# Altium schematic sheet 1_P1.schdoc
size 307 x 218 mm; Symbol: Drawing-Symbol_A4; Device: Drawing-Symbol_A4; Company: wenfeng110402; Drawed: 叶文峰; Reviewed: 叶文峰; Version: V1.0; Page Size: A4; @Project Name: hackpod; @Page Count: 1; @Update Date: 2025-11-23; @Create Date: 2025-11-21; @Schematic Name: Schematic1; @Page No: 1; @Page Name: P1; @Board Name: Board1; @Create Time: 22:44:27; @Update Time: 14:09:08; Title Block Position: 3; Size: A4; Width: 1170; Height: 825; Region Start: 1; X Region Count: 6; Y Region Count: 4; Blade Width: 10
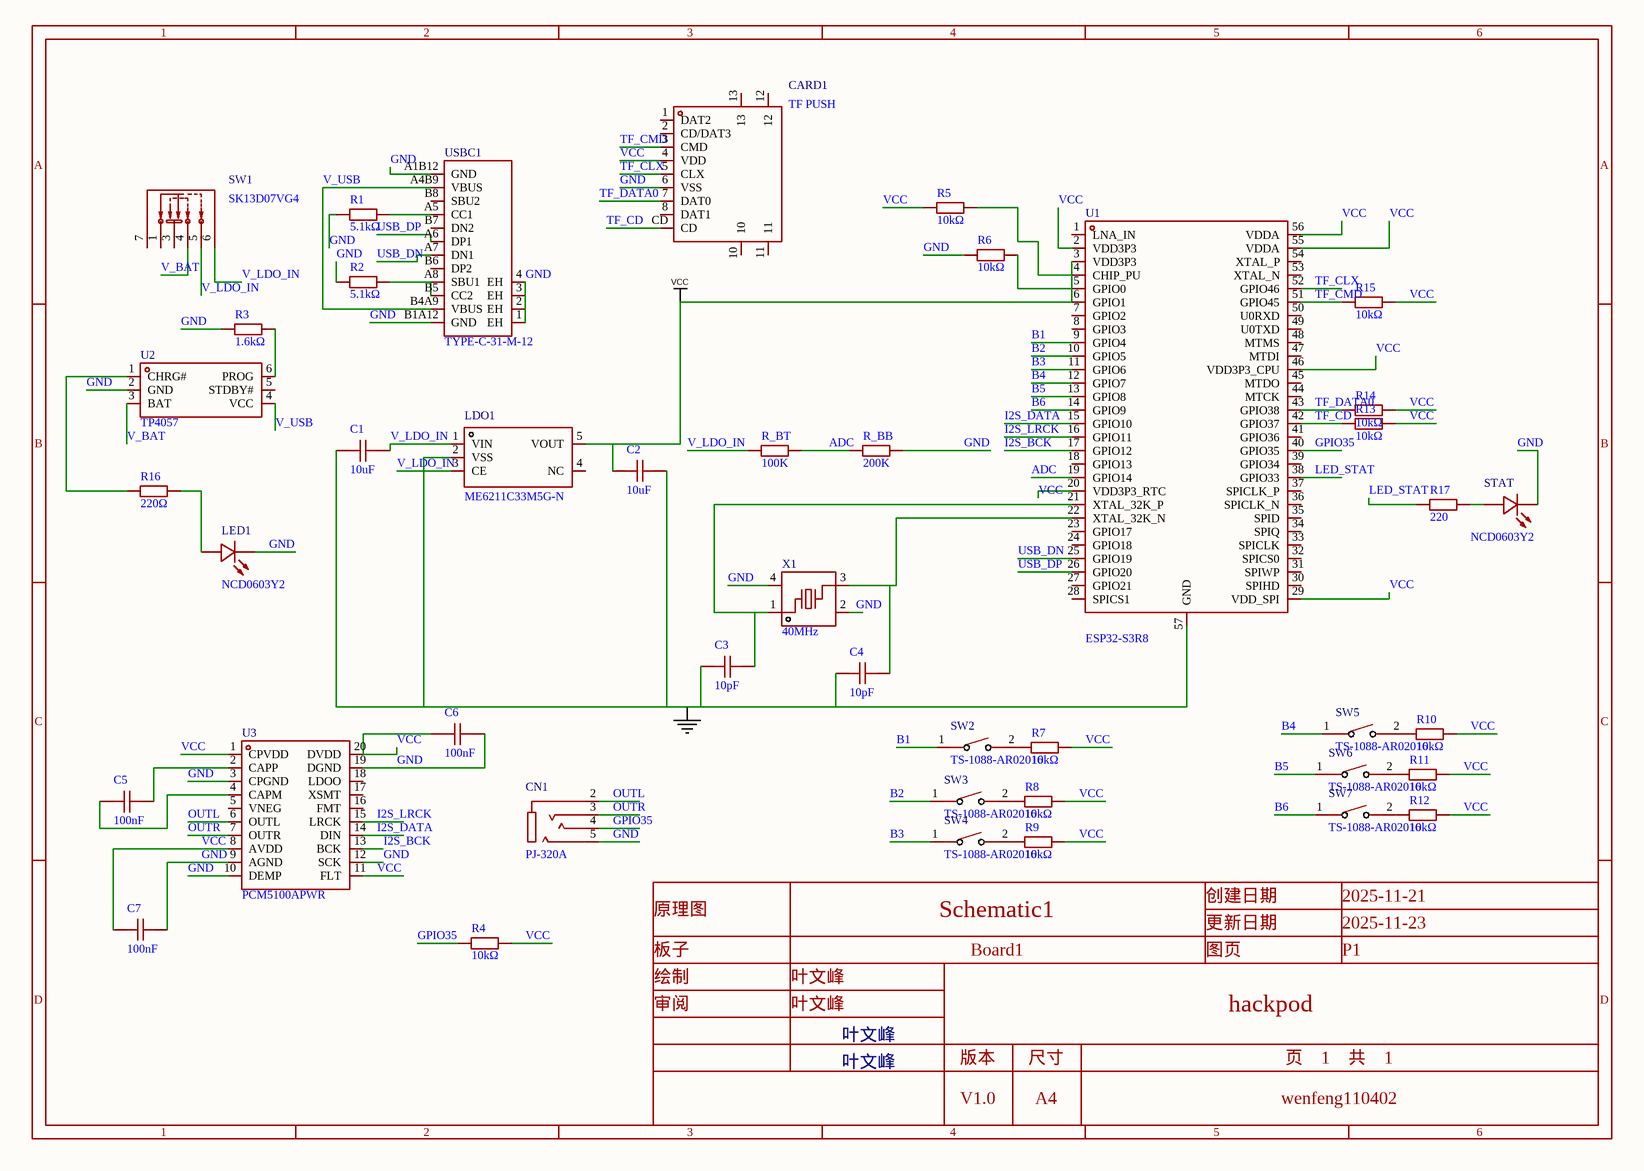
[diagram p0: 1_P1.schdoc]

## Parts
C1  10uF  [C0603]
C2  10uF  [C0603]
C3  10pF  [C0603]
C4  10pF  [C0603]
C5  100nF  [C0603]
C6  100nF  [C0603]
C7  100nF  [C0603]
CARD1  TF PUSH  [TF-SMD_TF-PUSH]
CN1  PJ-320A  [AUDIO-TH_PJ-320A_C49284721]
LDO1  ME6211C33M5G-N  [SOT-23-5_L3.0-W1.7-P0.95-LS2.8-BL]
LED1  NCD0603Y2  [LED0603-RD]
R1  5.1kΩ  [R0603]
R2  5.1kΩ  [R0603]
R3  1.6kΩ  [R0603]
R4  10kΩ  [R0603]
R5  10kΩ  [R0603]
R6  10kΩ  [R0603]
R7  10kΩ  [R0603]
R8  10kΩ  [R0603]
R9  10kΩ  [R0603]
R10  10kΩ  [R0603]
R11  10kΩ  [R0603]
R12  10kΩ  [R0603]
R13  10kΩ  [R0603]
R14  10kΩ  [R0603]
R15  10kΩ  [R0603]
R16  220Ω  [R0603]
R17  220  [R0603]
R_BB  200K  [R0603]
R_BT  100K  [R0603]
STAT  NCD0603Y2  [LED0603-RD]
SW1  SK13D07VG4  [SW-TH_SK13D07VG4]
SW2  TS-1088-AR02016  [SW-SMD_L3.9-W3.0-P4.45]
SW3  TS-1088-AR02016  [SW-SMD_L3.9-W3.0-P4.45]
SW4  TS-1088-AR02016  [SW-SMD_L3.9-W3.0-P4.45]
SW5  TS-1088-AR02016  [SW-SMD_L3.9-W3.0-P4.45]
SW6  TS-1088-AR02016  [SW-SMD_L3.9-W3.0-P4.45]
SW7  TS-1088-AR02016  [SW-SMD_L3.9-W3.0-P4.45]
U1  ESP32-S3R8  [QFN-56_L7.0-W7.0-P0.40-TL-EP4.0]
U2  TP4057  [SOT-23-6_L2.9-W1.6-P0.95-LS2.8-BR]
U3  PCM5100APWR  [TSSOP-20_L6.5-W4.4-P0.65-LS6.4-BL]
USBC1  TYPE-C-31-M-12  [USB-C_SMD-TYPE-C-31-M-12_1]
X1  40MHz  [CRYSTAL-SMD_4P-L3.2-W2.5-BL]

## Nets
GND: C1.1 C2.2 C3.1 C4.1 C6.2 C7.2 CARD1.6(VSS) CN1.5 LDO1.2(VSS) LED1.1(K) R1.1 R2.1 R3.1 R6.1 R_BB.2 STAT.1(K) U1.57(GND) U2.2(GND) U3.3(CPGND) U3.9(AGND) U3.10(DEMP) U3.12(SCK) U3.19(DGND) USBC1.1(EH) USBC1.2(EH) USBC1.3(EH) USBC1.4(EH) USBC1.A1B12(GND) USBC1.B1A12(GND) X1.2(GND) X1.4(GND)
VCC: C2.1 C6.1 C7.1 CARD1.4(VDD) LDO1.5(VOUT) R4.2 R5.1 R5.2 R6.2 R7.2 R8.2 R9.2 R10.2 R11.2 R12.2 R13.2 R14.2 R15.2 U1.2(VDD3P3) U1.3(VDD3P3) U1.4(CHIP_PU) U1.5(GPIO0) U1.6(GPIO1) U1.20(VDD3P3_RTC) U1.29(VDD_SPI) U1.46(VDD3P3_CPU) U1.55(VDDA) U1.56(VDDA) U3.1(CPVDD) U3.8(AVDD) U3.11(FLT) U3.20(DVDD)
ADC: R_BB.1 R_BT.2 U1.19(GPIO14)
B1: SW2.1 U1.9(GPIO4)
B2: SW3.1 U1.10(GPIO5)
B3: SW4.1 U1.11(GPIO6)
B4: SW5.1 U1.12(GPIO7)
B5: SW6.1 U1.13(GPIO8)
B6: SW7.1 U1.14(GPIO9)
GPIO35: CN1.4 R4.1 U1.40(GPIO35)
I2S_BCK: U1.17(GPIO12) U3.13(BCK)
I2S_DATA: U1.15(GPIO10) U3.14(DIN)
I2S_LRCK: U1.16(GPIO11) U3.15(LRCK)
LED_STAT: R17.1 U1.38(GPIO33)
OUTL: CN1.2 U3.6(OUTL)
OUTR: CN1.3 U3.7(OUTR)
TF_CD: CARD1.CD R13.1 U1.42(GPIO37)
TF_CLX: CARD1.5(CLX) U1.52(GPIO46)
TF_CMD: CARD1.3(CMD) R15.1 U1.51(GPIO45)
TF_DATA0: CARD1.7(DAT0) R14.1 U1.43(GPIO38)
USB_DN: U1.25(GPIO19) USBC1.A7(DN1)
USB_DP: U1.26(GPIO20) USBC1.A6(DP1)
V_BAT: SW1.4 U2.3(BAT)
V_LDO_IN: C1.2 LDO1.1(VIN) LDO1.3(CE) R_BT.1 SW1.5 SW1.6
V_USB: U2.4(VCC) USBC1.A4B9(VBUS) USBC1.B4A9(VBUS)
NetC3_2: C3.2 U1.21(XTAL_32K_P) X1.1
NetC4_2: C4.2 U1.22(XTAL_32K_N) X1.3
NetC5_1: C5.1 U3.4(CAPM)
NetC5_2: C5.2 U3.2(CAPP)
NetLED1_2: LED1.2(A) R16.2
NetR1_2: R1.2 USBC1.A5(CC1)
NetR2_2: R2.2 USBC1.A8(SBU1) USBC1.B5(CC2)
NetR3_2: R3.2 U2.6(PROG)
NetR7_1: R7.1 SW2.2
NetR8_1: R8.1 SW3.2
NetR9_1: R9.1 SW4.2
NetR10_1: R10.1 SW5.2
NetR11_1: R11.1 SW6.2
NetR12_1: R12.1 SW7.2
NetR16_1: R16.1 U2.1(CHRG#)
NetR17_2: R17.2 STAT.2(A)

Not connected (* = marked no-connect by the designer): CARD1 1(DAT2) 2(CD/DAT3) 8(DAT1) 10 11 12 13; LDO1 4(NC); SW1 1 3 7; U1 1(LNA_IN) 7(GPIO2) 8(GPIO3) 18(GPIO13) 23(GPIO17) 24(GPIO18) 27(GPIO21) 28(SPICS1) 30(SPIHD) 31(SPIWP) 32(SPICS0) 33(SPICLK) 34(SPIQ) 35(SPID) 36(SPICLK_N) 37(SPICLK_P) 39(GPIO34) 41(GPIO36) 44(MTCK) 45(MTDO) 47(MTDI) 48(MTMS) 49(U0TXD) 50(U0RXD) 53(XTAL_N) 54(XTAL_P); U2 5(STDBY#); U3 5(VNEG) 16(FMT) 17(XSMT) 18(LDOO); USBC1 B6(DP2) B7(DN2) B8(SBU2)

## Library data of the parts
C1 = CL10A106MA8NRNC: Manufacturer: SAMSUNG(三星); Symbol: Capacitance; Add into BOM: yes; Tolerance: ±20%; Voltage Rating: 25V; Temperature Coefficient: X5R; Channel ID: $1e742
C2 = CL10A106MA8NRNC: Manufacturer: SAMSUNG(三星); Symbol: Capacitance; Add into BOM: yes; Tolerance: ±20%; Voltage Rating: 25V; Temperature Coefficient: X5R; Channel ID: $1e772
C3 = CL10C100JB8NNNC: Manufacturer: SAMSUNG(三星); Symbol: Capacitance; Add into BOM: yes; Tolerance: ±5%; Voltage Rating: 50V; Temperature Coefficient: C0G; Channel ID: $1e1234
C4 = CL10C100JB8NNNC: Manufacturer: SAMSUNG(三星); Symbol: Capacitance; Add into BOM: yes; Tolerance: ±5%; Voltage Rating: 50V; Temperature Coefficient: C0G; Channel ID: $1e1264
C5 = CL10B104KB8NNNC: Manufacturer: SAMSUNG(三星); Symbol: Capacitance; Add into BOM: yes; Tolerance: ±10%; Voltage Rating: 50V; Temperature Coefficient: X7R; Channel ID: $1e2786
C6 = CL10B104KB8NNNC: Manufacturer: SAMSUNG(三星); Symbol: Capacitance; Add into BOM: yes; Tolerance: ±10%; Voltage Rating: 50V; Temperature Coefficient: X7R; Channel ID: $1e3067
C7 = CL10B104KB8NNNC: Manufacturer: SAMSUNG(三星); Symbol: Capacitance; Add into BOM: yes; Tolerance: ±10%; Voltage Rating: 50V; Temperature Coefficient: X7R; Channel ID: $1e3097
CARD1 = TF PUSH: Manufacturer: SHOU HAN(首韩); Add into BOM: yes; Card Connection Mode: 自弹式; Card Type: MicroSD卡(TF卡); Connector Type: 卡座; Additional Card Detection Pins: 无
CN1 = PJ-320A_C49284721: Manufacturer: XUNPU(讯普); Add into BOM: yes; Connector Type: 3.5mm耳机座; Current Rating: 500mA; Voltage Rating (Max): 30V
LDO1 = ME6211C33M5G-N: Manufacturer: MICRONE(南京微盟); Add into BOM: yes; Output Type: 固定; Voltage - Supply: 6V; Output Voltage: 3.3V; Output Current: 500mA; Power Supply Rejection Ratio (PSRR): 70dB@(1kHz); Voltage Dropout: 120mV@(100mA); standby current: 60uA; Noise: 50uVrms; Output Configuration: 正极; Number of Outputs: 1
LED1 STAT = NCD0603Y2: Manufacturer: 国星光电; Symbol: FC-1608YXK-585F08; Add into BOM: yes; Emitted Color: 黄色; Forward Voltage (VF): 1.6V~2.6V; Power Dissipation: 65mW; Forward Current: 20mA; Dominant Wavelength: 586nm~595nm; Lens Color: 无色透明透镜; Luminous Intensity: 100mcd~220mcd; Viewing Angle: 130°
R1 = 0603WAF5101T5E: Manufacturer: UNI-ROYAL(厚声); Symbol: 电阻; Add into BOM: yes; Tolerance: ±1%; Power(Watts): 100mW; Voltage-Supply(Max): 75V; Temperature Coefficient: ±100ppm/℃; Channel ID: $1e1980
R2 = 0603WAF5101T5E: Manufacturer: UNI-ROYAL(厚声); Symbol: 电阻; Add into BOM: yes; Tolerance: ±1%; Power(Watts): 100mW; Voltage-Supply(Max): 75V; Temperature Coefficient: ±100ppm/℃; Channel ID: $1e2010
R3 = ERA3AEB162V: Manufacturer: PANASONIC(松下); Symbol: 电阻; Add into BOM: yes; Tolerance: ±0.1%; Power(Watts): 100mW; Overload Voltage (Max): 75V; Temperature Coefficient: ±25ppm/℃; Channel ID: $1e2136
R4 = 0603WAF1002T5E: Manufacturer: UNI-ROYAL(厚声); Symbol: 电阻; Add into BOM: yes; Tolerance: ±1%; Power(Watts): 100mW; Voltage-Supply(Max): 75V; Temperature Coefficient: ±100ppm/℃; Channel ID: $1e3195
R5 = 0603WAF1002T5E: Manufacturer: UNI-ROYAL(厚声); Symbol: 电阻; Add into BOM: yes; Tolerance: ±1%; Power(Watts): 100mW; Voltage-Supply(Max): 75V; Temperature Coefficient: ±100ppm/℃; Channel ID: $1e3264
R6 = 0603WAF1002T5E: Manufacturer: UNI-ROYAL(厚声); Symbol: 电阻; Add into BOM: yes; Tolerance: ±1%; Power(Watts): 100mW; Voltage-Supply(Max): 75V; Temperature Coefficient: ±100ppm/℃; Channel ID: $1e3294
R7 = 0603WAF1002T5E: Manufacturer: UNI-ROYAL(厚声); Symbol: 电阻; Add into BOM: yes; Tolerance: ±1%; Power(Watts): 100mW; Voltage-Supply(Max): 75V; Temperature Coefficient: ±100ppm/℃; Channel ID: $1e3738
R8 = 0603WAF1002T5E: Manufacturer: UNI-ROYAL(厚声); Symbol: 电阻; Add into BOM: yes; Tolerance: ±1%; Power(Watts): 100mW; Voltage-Supply(Max): 75V; Temperature Coefficient: ±100ppm/℃; Channel ID: $1e3770
R9 = 0603WAF1002T5E: Manufacturer: UNI-ROYAL(厚声); Symbol: 电阻; Add into BOM: yes; Tolerance: ±1%; Power(Watts): 100mW; Voltage-Supply(Max): 75V; Temperature Coefficient: ±100ppm/℃; Channel ID: $1e3802
R10 = 0603WAF1002T5E: Manufacturer: UNI-ROYAL(厚声); Symbol: 电阻; Add into BOM: yes; Tolerance: ±1%; Power(Watts): 100mW; Voltage-Supply(Max): 75V; Temperature Coefficient: ±100ppm/℃; Channel ID: $1e3834
R11 = 0603WAF1002T5E: Manufacturer: UNI-ROYAL(厚声); Symbol: 电阻; Add into BOM: yes; Tolerance: ±1%; Power(Watts): 100mW; Voltage-Supply(Max): 75V; Temperature Coefficient: ±100ppm/℃; Channel ID: $1e3866
R12 = 0603WAF1002T5E: Manufacturer: UNI-ROYAL(厚声); Symbol: 电阻; Add into BOM: yes; Tolerance: ±1%; Power(Watts): 100mW; Voltage-Supply(Max): 75V; Temperature Coefficient: ±100ppm/℃; Channel ID: $1e3898
R13 = 0603WAF1002T5E: Manufacturer: UNI-ROYAL(厚声); Symbol: 电阻; Add into BOM: yes; Tolerance: ±1%; Power(Watts): 100mW; Voltage-Supply(Max): 75V; Temperature Coefficient: ±100ppm/℃; Channel ID: $1e4291
R14 = 0603WAF1002T5E: Manufacturer: UNI-ROYAL(厚声); Symbol: 电阻; Add into BOM: yes; Tolerance: ±1%; Power(Watts): 100mW; Voltage-Supply(Max): 75V; Temperature Coefficient: ±100ppm/℃; Channel ID: $1e4321
R15 = 0603WAF1002T5E: Manufacturer: UNI-ROYAL(厚声); Symbol: 电阻; Add into BOM: yes; Tolerance: ±1%; Power(Watts): 100mW; Voltage-Supply(Max): 75V; Temperature Coefficient: ±100ppm/℃; Channel ID: $1e4351
R16 = FRC0603J221 TS: Manufacturer: FOJAN(富捷); Symbol: 电阻; Add into BOM: yes; Tolerance: ±5%; Power(Watts): 100mW; Voltage-Supply(Max): 75V; Temperature Coefficient: ±100ppm/℃; Channel ID: $1e4502
R17 R_BB R_BT = Res_0603: Symbol: 电阻; Convert to PCB: yes
SW1 = SK13D07VG4: Manufacturer: SHOU HAN(首韩); Add into BOM: yes; Circuit: 单刀三掷; Switch Height: 4.7mm; Current Rating: 300mA; Voltage Rating: 50V; Life: 5千次
SW2-SW7 = TS-1088-AR02016: Manufacturer: XUNPU(讯普); Add into BOM: yes; Circuit: 单刀单掷; Actuator Style: 圆形按钮; Operating Force: 1.6N; Switch Height: 2mm; with Bracket: 不带支架; Contact Current: 50mA; Voltage Rating: 12V; Actuator/Cap Color: 黑色; Life: 10万次
U1 = ESP32-S3R8: Manufacturer: ESPRESSIF(乐鑫); Symbol: ESP32-S3(R8); Add into BOM: yes; Frequency Range: 2.412GHz~2.484GHz; Interface: I2C；I2S；UART；USB；SPI; Voltage - Supply: 3V~3.6V; Output Power: 18.5dBm; Data Rate: 150Mbps; Current Of Transmitting: 283mA; Sensitivity: -74.2dBm; Receive Current: 88mA; Typical Application Frequency: 2.4GHz
U2 = TP4057: Manufacturer: UMW(友台半导体); Symbol: TP4057_C725791; Add into BOM: yes; The Chip Type: 充电芯片; Voltage - Supply: 4V~6.5V; Charge Current - Max: 500mA; Charging Saturation Voltage: 4.24V; Type of Battery: 锂离子; Number of Cells: 1; Battery Temperature Detection: 支持; Supply Current (Iq): 25uA
U3 = PCM5100APWR: Manufacturer: TI(德州仪器); Add into BOM: yes; Voltage - Supply: 1.8V~3.3V; Interface Type: I2S
USBC1 = TYPE-C-31-M-12: Manufacturer: 韩国韩荣; Add into BOM: yes; Connector Type: Type-C; Gender: 母; Number of Contacts: 16P; Number of Ports: 1; Current Rating-Power: 5A
X1 = XL2EL89CPI-111YLC-40M: Manufacturer: YXC(扬兴晶振); Add into BOM: yes; Normal temperature Frequency Tolerance: ±10ppm; Load Capacitance: 15pF; Frequency Stability: ±20ppm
